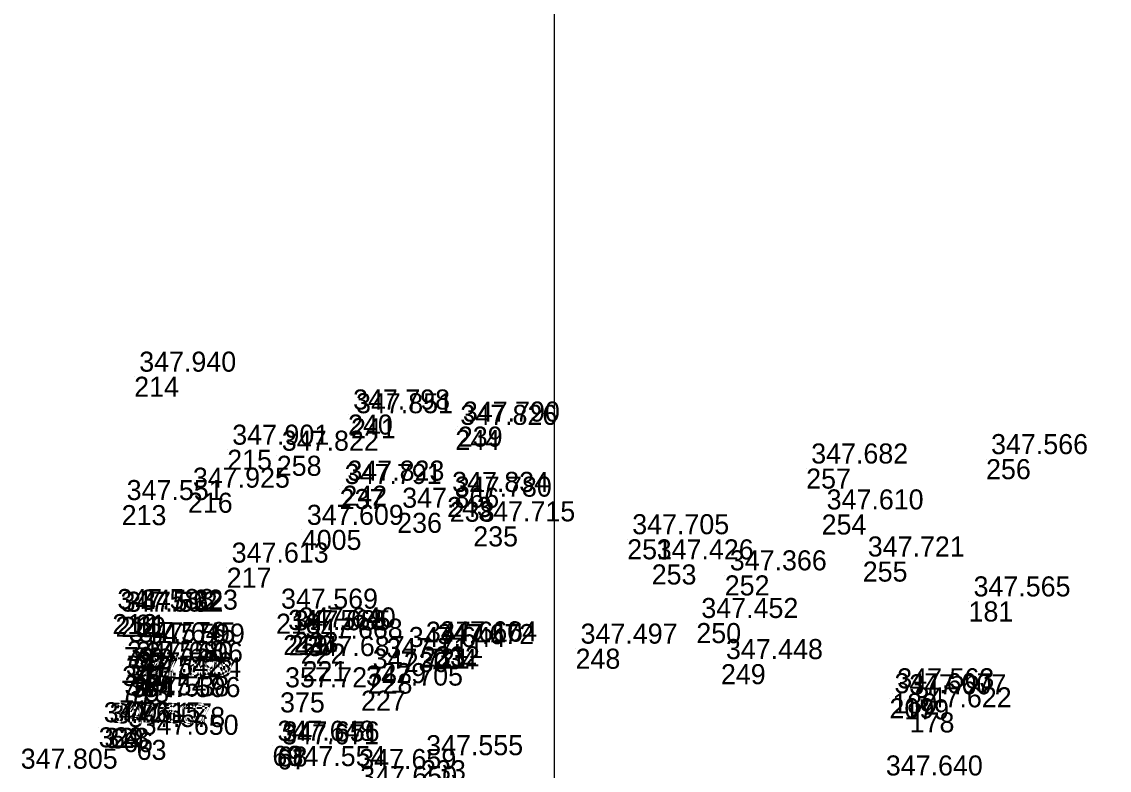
# Model space of a CAD drawing. Extents: x -829398 to -819400, y -1074439 to -1067977.
# Drawn here: x -822731.9 to -822666.8, y -1072246.3 to -1072201.6 of the extents above; entities that cross this region are included whole.
import ezdxf

# ---------------------------------------------------------------- set-up
doc = ezdxf.new("R2010")
doc.units = 0
doc.layers.add('Vrstva 60', color=7, linetype='Continuous')
doc.layers.add('Vrstva 61', color=7, linetype='Continuous')

msp = doc.modelspace()

# ---------------------------------------------------------------- linework, layer by layer
at = {"layer": 'Vrstva 60'}
for p, q in [((-822725.124, -1072222.806), (-822725.124, -1072222.806)), ((-822712.332, -1072225.068), (-822712.332, -1072225.068)), ((-822712.155, -1072225.29), (-822712.155, -1072225.29)), ((-822705.916, -1072225.986), (-822705.916, -1072225.986)), ((-822705.763, -1072225.789), (-822705.763, -1072225.789)), ((-822719.56, -1072227.173), (-822719.56, -1072227.173)), ((-822716.595, -1072227.533), (-822716.595, -1072227.533)), ((-822674.166, -1072227.736), (-822674.166, -1072227.736)), ((-822684.926, -1072228.298), (-822684.926, -1072228.298)), ((-822712.67, -1072229.321), (-822712.67, -1072229.321)), ((-822721.911, -1072229.743), (-822721.911, -1072229.743)), ((-822712.833, -1072229.522), (-822712.833, -1072229.522)), ((-822706.407, -1072229.996), (-822706.407, -1072229.996)), ((-822725.876, -1072230.484), (-822725.876, -1072230.484)), ((-822706.247, -1072230.28), (-822706.247, -1072230.28)), ((-822709.392, -1072230.944), (-822709.392, -1072230.944)), ((-822684.002, -1072231.045), (-822684.002, -1072231.045)), ((-822715.098, -1072231.965), (-822715.098, -1072231.965)), ((-822704.842, -1072231.757), (-822704.842, -1072231.757)), ((-822695.632, -1072232.527), (-822695.632, -1072232.527)), ((-822694.167, -1072234.032), (-822694.167, -1072234.032)), ((-822681.542, -1072233.86), (-822681.542, -1072233.86)), ((-822719.592, -1072234.225), (-822719.592, -1072234.225)), ((-822689.796, -1072234.688), (-822689.796, -1072234.688)), ((-822675.213, -1072236.247), (-822675.213, -1072236.247)), ((-822726.434, -1072237.003), (-822726.434, -1072237.003)), ((-822726.241, -1072237.154), (-822726.241, -1072237.154)), ((-822725.9, -1072237.164), (-822725.9, -1072237.164)), ((-822725.02, -1072237.039), (-822725.02, -1072237.039)), ((-822716.642, -1072236.978), (-822716.642, -1072236.978)), ((-822691.497, -1072237.537), (-822691.497, -1072237.537)), ((-822716.214, -1072238.254), (-822716.214, -1072238.254)), ((-822715.883, -1072238.272), (-822715.883, -1072238.272)), ((-822715.576, -1072238.102), (-822715.576, -1072238.102)), ((-822725.745, -1072238.971), (-822725.745, -1072238.971)), ((-822725.171, -1072239.003), (-822725.171, -1072239.003)), ((-822724.606, -1072239.07), (-822724.606, -1072239.07)), ((-822715.165, -1072238.772), (-822715.165, -1072238.772)), ((-822707.973, -1072238.954), (-822707.973, -1072238.954)), ((-822707.302, -1072239.099), (-822707.302, -1072239.099)), ((-822707.125, -1072238.934), (-822707.125, -1072238.934)), ((-822698.72, -1072239.072), (-822698.72, -1072239.072)), ((-822715.051, -1072239.817), (-822715.051, -1072239.817)), ((-822708.999, -1072239.273), (-822708.999, -1072239.273)), ((-822725.844, -1072240.105), (-822725.844, -1072240.105)), ((-822725.302, -1072240.143), (-822725.302, -1072240.143)), ((-822724.726, -1072240.187), (-822724.726, -1072240.187)), ((-822710.338, -1072239.933), (-822710.338, -1072239.933)), ((-822690.025, -1072239.996), (-822690.025, -1072239.996)), ((-822725.92, -1072240.987), (-822725.92, -1072240.987)), ((-822725.408, -1072241.049), (-822725.408, -1072241.049)), ((-822725.338, -1072240.782), (-822725.338, -1072240.782)), ((-822724.823, -1072241.087), (-822724.823, -1072241.087)), ((-822711.157, -1072240.562), (-822711.157, -1072240.562)), ((-822716.401, -1072241.685), (-822716.401, -1072241.685)), ((-822711.556, -1072241.58), (-822711.556, -1072241.58)), ((-822679.776, -1072241.743), (-822679.776, -1072241.743)), ((-822726.007, -1072242.161), (-822726.007, -1072242.161)), ((-822725.541, -1072242.218), (-822725.541, -1072242.218)), ((-822724.87, -1072242.266), (-822724.87, -1072242.266)), ((-822679.943, -1072242.037), (-822679.943, -1072242.037)), ((-822679.058, -1072242.103), (-822679.058, -1072242.103)), ((-822678.735, -1072242.88), (-822678.735, -1072242.88)), ((-822727.25, -1072243.774), (-822727.25, -1072243.774)), ((-822726.901, -1072243.81), (-822726.901, -1072243.81)), ((-822726.572, -1072243.842), (-822726.572, -1072243.842)), ((-822725.785, -1072244.059), (-822725.785, -1072244.059)), ((-822724.98, -1072244.524), (-822724.98, -1072244.524)), ((-822716.856, -1072244.881), (-822716.856, -1072244.881)), ((-822716.582, -1072245.092), (-822716.582, -1072245.092)), ((-822716.544, -1072244.922), (-822716.544, -1072244.922)), ((-822707.96, -1072245.743), (-822707.96, -1072245.743))]:
    msp.add_line(p, q, dxfattribs=at)
at = {"layer": 'Vrstva 61'}
msp.add_lwpolyline([(-822200, -1071700), (-822700, -1071700), (-822700, -1072400), (-822200, -1072400)], close=True, dxfattribs=at)

# ---------------------------------------------------------------- texts
at = {"layer": 'Vrstva 60'}
for s, p in [('214', (-822725.124, -1072224.006)), ('240', (-822712.332, -1072226.268)), ('241', (-822712.155, -1072226.49)), ('244', (-822705.916, -1072227.186)), ('239', (-822705.763, -1072226.989)), ('215', (-822719.56, -1072228.373)), ('258', (-822716.595, -1072228.733)), ('256', (-822674.166, -1072228.936)), ('257', (-822684.926, -1072229.498)), ('242', (-822712.67, -1072230.521)), ('216', (-822721.911, -1072230.943)), ('237', (-822712.833, -1072230.722)), ('243', (-822706.407, -1072231.196)), ('213', (-822725.876, -1072231.684)), ('238', (-822706.247, -1072231.48)), ('236', (-822709.392, -1072232.144)), ('254', (-822684.002, -1072232.245)), ('4005', (-822715.098, -1072233.165)), ('235', (-822704.842, -1072232.957)), ('251', (-822695.632, -1072233.727)), ('253', (-822694.167, -1072235.232)), ('255', (-822681.542, -1072235.06)), ('217', (-822719.592, -1072235.425)), ('252', (-822689.796, -1072235.888)), ('181', (-822675.213, -1072237.447)), ('212', (-822726.434, -1072238.203)), ('211', (-822726.241, -1072238.354)), ('210', (-822725.9, -1072238.364)), ('81', (-822725.02, -1072238.239)), ('218', (-822716.642, -1072238.178)), ('250', (-822691.497, -1072238.737)), ('219', (-822716.214, -1072239.454)), ('220', (-822715.883, -1072239.472)), ('223', (-822715.576, -1072239.302)), ('79', (-822725.745, -1072240.171)), ('80', (-822725.171, -1072240.203)), ('78', (-822724.606, -1072240.27)), ('222', (-822715.165, -1072239.972)), ('231', (-822707.973, -1072240.154)), ('234', (-822707.302, -1072240.299)), ('232', (-822707.125, -1072240.134)), ('248', (-822698.72, -1072240.272)), ('221', (-822715.051, -1072241.017)), ('230', (-822708.999, -1072240.473)), ('341', (-822725.844, -1072241.305)), ('76', (-822725.302, -1072241.343)), ('77', (-822724.726, -1072241.387)), ('228', (-822711.157, -1072241.762)), ('229', (-822710.338, -1072241.133)), ('249', (-822690.025, -1072241.196)), ('74', (-822725.92, -1072242.187)), ('75', (-822725.408, -1072242.249)), ('374', (-822725.338, -1072241.982)), ('73', (-822724.823, -1072242.287)), ('375', (-822716.401, -1072242.885)), ('227', (-822711.556, -1072242.78)), ('180', (-822679.776, -1072242.943)), ('71', (-822726.007, -1072243.361)), ('70', (-822725.541, -1072243.418)), ('72', (-822724.87, -1072243.466)), ('209', (-822679.943, -1072243.237)), ('179', (-822679.058, -1072243.303)), ('178', (-822678.735, -1072244.08)), ('329', (-822727.25, -1072244.974)), ('328', (-822726.901, -1072245.01)), ('64', (-822726.572, -1072245.042)), ('66', (-822725.785, -1072245.259)), ('63', (-822724.98, -1072245.724)), ('69', (-822716.856, -1072246.081)), ('67', (-822716.582, -1072246.292)), ('68', (-822716.544, -1072246.122)), ('233', (-822707.96, -1072246.943))]:
    msp.add_text(s, height=1.2, dxfattribs=at).set_placement(p)
at = {"layer": 'Vrstva 61'}
for s, p in [('347.940', (-822724.824, -1072222.506)), ('347.798', (-822712.032, -1072224.768)), ('347.851', (-822711.855, -1072224.99)), ('347.790', (-822705.463, -1072225.489)), ('347.826', (-822705.616, -1072225.686)), ('347.901', (-822719.26, -1072226.873)), ('347.822', (-822716.295, -1072227.233)), ('347.566', (-822673.866, -1072227.436)), ('347.682', (-822684.626, -1072227.998)), ('347.791', (-822712.533, -1072229.222)), ('347.823', (-822712.37, -1072229.021)), ('347.925', (-822721.611, -1072229.443)), ('347.834', (-822706.107, -1072229.696)), ('347.780', (-822705.947, -1072229.98)), ('347.551', (-822725.576, -1072230.184)), ('347.866', (-822709.092, -1072230.644)), ('347.610', (-822683.702, -1072230.745)), ('347.609', (-822714.798, -1072231.665)), ('347.715', (-822704.542, -1072231.457)), ('347.705', (-822695.332, -1072232.227)), ('347.613', (-822719.292, -1072233.925)), ('347.426', (-822693.867, -1072233.732)), ('347.721', (-822681.242, -1072233.56)), ('347.366', (-822689.496, -1072234.388)), ('347.565', (-822674.913, -1072235.947)), ('347.588', (-822726.134, -1072236.703)), ('347.592', (-822725.941, -1072236.854)), ('347.532', (-822725.6, -1072236.864)), ('347.623', (-822724.72, -1072236.739)), ('347.569', (-822716.342, -1072236.678)), ('347.640', (-822715.276, -1072237.802)), ('347.452', (-822691.197, -1072237.237)), ('347.568', (-822715.914, -1072237.954)), ('347.685', (-822715.583, -1072237.972)), ('347.668', (-822714.865, -1072238.472)), ('347.576', (-822725.445, -1072238.671)), ('347.645', (-822724.871, -1072238.703)), ('347.599', (-822724.306, -1072238.77)), ('347.644', (-822708.699, -1072238.973)), ('347.616', (-822707.673, -1072238.654)), ('347.672', (-822707.002, -1072238.799)), ('347.604', (-822706.825, -1072238.634)), ('347.497', (-822698.42, -1072238.772)), ('347.558', (-822725.544, -1072239.805)), ('347.687', (-822714.751, -1072239.517)), ('347.711', (-822710.038, -1072239.633)), ('347.448', (-822689.725, -1072239.696)), ('347.680', (-822725.002, -1072239.843)), ('347.606', (-822724.426, -1072239.887)), ('347.721', (-822710.857, -1072240.262)), ('347.542', (-822725.62, -1072240.687)), ('347.695', (-822725.108, -1072240.749)), ('357.706', (-822725.038, -1072240.482)), ('347.604', (-822724.523, -1072240.787)), ('357.727', (-822716.101, -1072241.385)), ('347.705', (-822711.256, -1072241.28)), ('347.607', (-822679.643, -1072241.737)), ('347.563', (-822679.476, -1072241.443)), ('347.547', (-822725.707, -1072241.861)), ('347.538', (-822725.241, -1072241.918)), ('347.596', (-822724.57, -1072241.966)), ('347.607', (-822678.758, -1072241.803)), ('347.622', (-822678.435, -1072242.58)), ('347.615', (-822726.95, -1072243.474)), ('347.612', (-822726.601, -1072243.51)), ('347.607', (-822726.272, -1072243.542)), ('347.578', (-822725.485, -1072243.759)), ('347.650', (-822724.68, -1072244.224)), ('347.648', (-822716.556, -1072244.581)), ('347.671', (-822716.282, -1072244.792)), ('347.656', (-822716.244, -1072244.622)), ('347.555', (-822707.66, -1072245.443)), ('347.805', (-822731.913, -1072246.25)), ('347.554', (-822715.894, -1072246.094)), ('347.659', (-822711.661, -1072246.271)), ('347.640', (-822680.161, -1072246.656)), ('347.650', (-822711.606, -1072247.291))]:
    msp.add_text(s, height=1.2, dxfattribs=at).set_placement(p)

doc.saveas('drawing.dxf')
